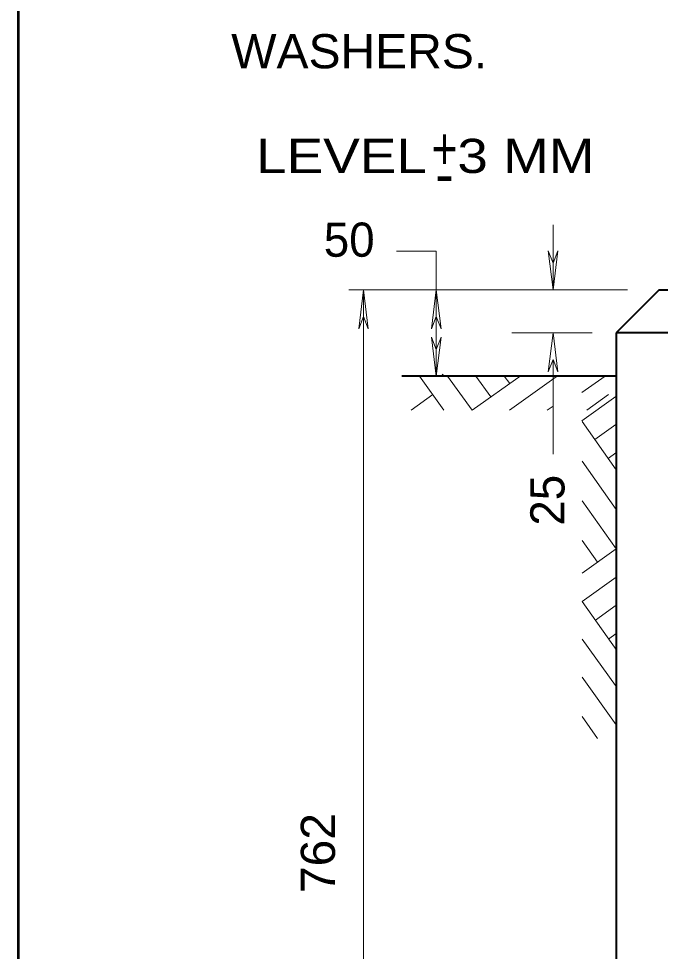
# Model space of a CAD drawing. Extents: x 312583 to 312854, y 144419 to 144597.
# Drawn here: x 312691.98 to 312706.25, y 144494.68 to 144515.42 of the extents above; entities that cross this region are included whole.
import ezdxf
from ezdxf.enums import TextEntityAlignment as Align

# ---------------------------------------------------------------- set-up
doc = ezdxf.new("R2010")
doc.units = 0
doc.header["$LTSCALE"] = 0.3
doc.layers.add('1', color=7, linetype='Continuous', lineweight=25)
doc.layers.add('2', color=7, linetype='Continuous', lineweight=13)

msp = doc.modelspace()

# ---------------------------------------------------------------- linework, layer by layer
at = {"layer": '1', "lineweight": 53}
msp.add_line((312691.9772, 144423.0846), (312691.9772, 144585.0846), dxfattribs=at)
at = {"layer": '1', "lineweight": 40}
for p, q in [((312706.2239, 144509.3872), (312705.2655, 144508.4289)), ((312706.2239, 144509.3872), (312721.5572, 144509.3872)), ((312705.2655, 144508.4289), (312705.2655, 144480.6372)), ((312708.6465, 144508.4289), (312705.2655, 144508.4289)), ((312705.2655, 144507.4705), (312700.4969, 144507.4705))]:
    msp.add_line(p, q, dxfattribs=at)
at = {"layer": '2'}
for p, q in [((312703.8625, 144509.3872), (312703.8625, 144510.8362)), ((312700.3813, 144510.2459), (312701.2635, 144510.2459)), ((312701.2635, 144507.4705), (312701.2635, 144510.2459)), ((312703.7552, 144510.2535), (312703.8625, 144509.9775)), ((312703.8625, 144509.3872), (312703.7552, 144510.2535)), ((312703.9699, 144510.2535), (312703.8625, 144509.9775)), ((312703.8625, 144509.3872), (312703.9699, 144510.2535)), ((312705.5185, 144509.3872), (312699.3162, 144509.3872)), ((312699.6459, 144509.3872), (312699.5385, 144508.5209)), ((312699.6459, 144480.6372), (312699.6459, 144509.3872)), ((312699.6459, 144509.3872), (312699.7532, 144508.5209)), ((312701.2635, 144509.3872), (312701.1562, 144508.5209)), ((312701.2635, 144509.3872), (312701.3709, 144508.5209)), ((312699.5385, 144508.5209), (312699.6459, 144508.7969)), ((312699.7532, 144508.5209), (312699.6459, 144508.7969)), ((312701.1562, 144508.5209), (312701.2635, 144508.7969)), ((312701.3709, 144508.5209), (312701.2635, 144508.7969)), ((312704.7289, 144508.4289), (312702.9425, 144508.4289)), ((312703.8625, 144508.4289), (312703.7552, 144507.5625)), ((312703.8625, 144508.4289), (312703.9699, 144507.5625)), ((312701.1562, 144508.3369), (312701.2635, 144508.0609)), ((312701.2635, 144507.4705), (312701.1562, 144508.3369)), ((312701.3709, 144508.3369), (312701.2635, 144508.0609)), ((312701.2635, 144507.4705), (312701.3709, 144508.3369)), ((312703.7552, 144507.5625), (312703.8625, 144507.8385)), ((312703.8625, 144505.7302), (312703.8625, 144507.8385)), ((312703.9699, 144507.5625), (312703.8625, 144507.8385)), ((312700.8879, 144507.4705), (312701.4322, 144506.7115)), ((312701.4399, 144507.4782), (312701.3939, 144507.5089)), ((312701.5165, 144507.4705), (312702.0609, 144506.7115)), ((312702.0609, 144506.7115), (312703.1495, 144507.4859)), ((312702.1452, 144507.4705), (312702.4749, 144507.0105)), ((312702.7739, 144507.4705), (312702.8965, 144507.3019)), ((312702.8889, 144506.7115), (312703.9315, 144507.4552)), ((312705.0202, 144507.4705), (312704.4989, 144507.1025)), ((312700.7039, 144506.7115), (312701.1869, 144507.0565)), ((312705.2579, 144507.0182), (312704.4989, 144506.4739)), ((312704.6139, 144506.7115), (312705.0969, 144507.0565)), ((312703.7322, 144506.7115), (312703.8625, 144506.8035)), ((312704.5065, 144506.4585), (312705.2655, 144505.3852)), ((312705.2579, 144506.3895), (312704.7902, 144506.0599)), ((312705.2579, 144505.7609), (312705.0892, 144505.6382)), ((312704.5065, 144505.5769), (312705.2655, 144504.5035)), ((312704.5065, 144504.6952), (312705.2655, 144503.6295)), ((312704.5065, 144503.8135), (312704.8515, 144503.3305)), ((312705.2655, 144503.6295), (312704.5065, 144503.0852)), ((312705.2655, 144503.0009), (312704.5065, 144502.4565)), ((312704.5065, 144502.4565), (312705.2809, 144501.3679)), ((312705.2655, 144502.3722), (312704.8055, 144502.0425)), ((312704.5065, 144501.6209), (312705.2502, 144500.5859)), ((312705.2655, 144501.7435), (312705.0969, 144501.6209)), ((312704.5065, 144500.7775), (312705.2655, 144499.7119)), ((312704.5065, 144499.9035), (312704.8515, 144499.4129))]:
    msp.add_line(p, q, dxfattribs=at)

# ---------------------------------------------------------------- texts
for s, width, p in [('WASHERS. ', 1.05, (312696.7045, 144514.3131)), ('LEVEL  3 MM', 1.2, (312697.2584, 144511.9854))]:
    msp.add_text(s, height=0.76, dxfattribs=dict(at, width=width)).set_placement(p)
at = {"layer": '2', "width": 0.8}
msp.add_text('+', height=0.92, rotation=180, dxfattribs=at).set_placement((312701.4475, 144512.9599), align=Align.CENTER)
at = {"layer": '2'}
msp.add_text('-', height=0.92, rotation=180, dxfattribs=at).set_placement((312701.4476, 144512.2162), align=Align.CENTER)
msp.add_text('50', height=0.76, dxfattribs=at).set_placement((312698.7628, 144510.1234))
msp.add_text('25', height=0.76, rotation=90, dxfattribs=at).set_placement((312704.1152, 144504.1436))
at = {"layer": '2', "width": 1.05}
msp.add_text('762', height=0.76, rotation=90, dxfattribs=at).set_placement((312699.012, 144495.9728))

doc.saveas('drawing.dxf')
